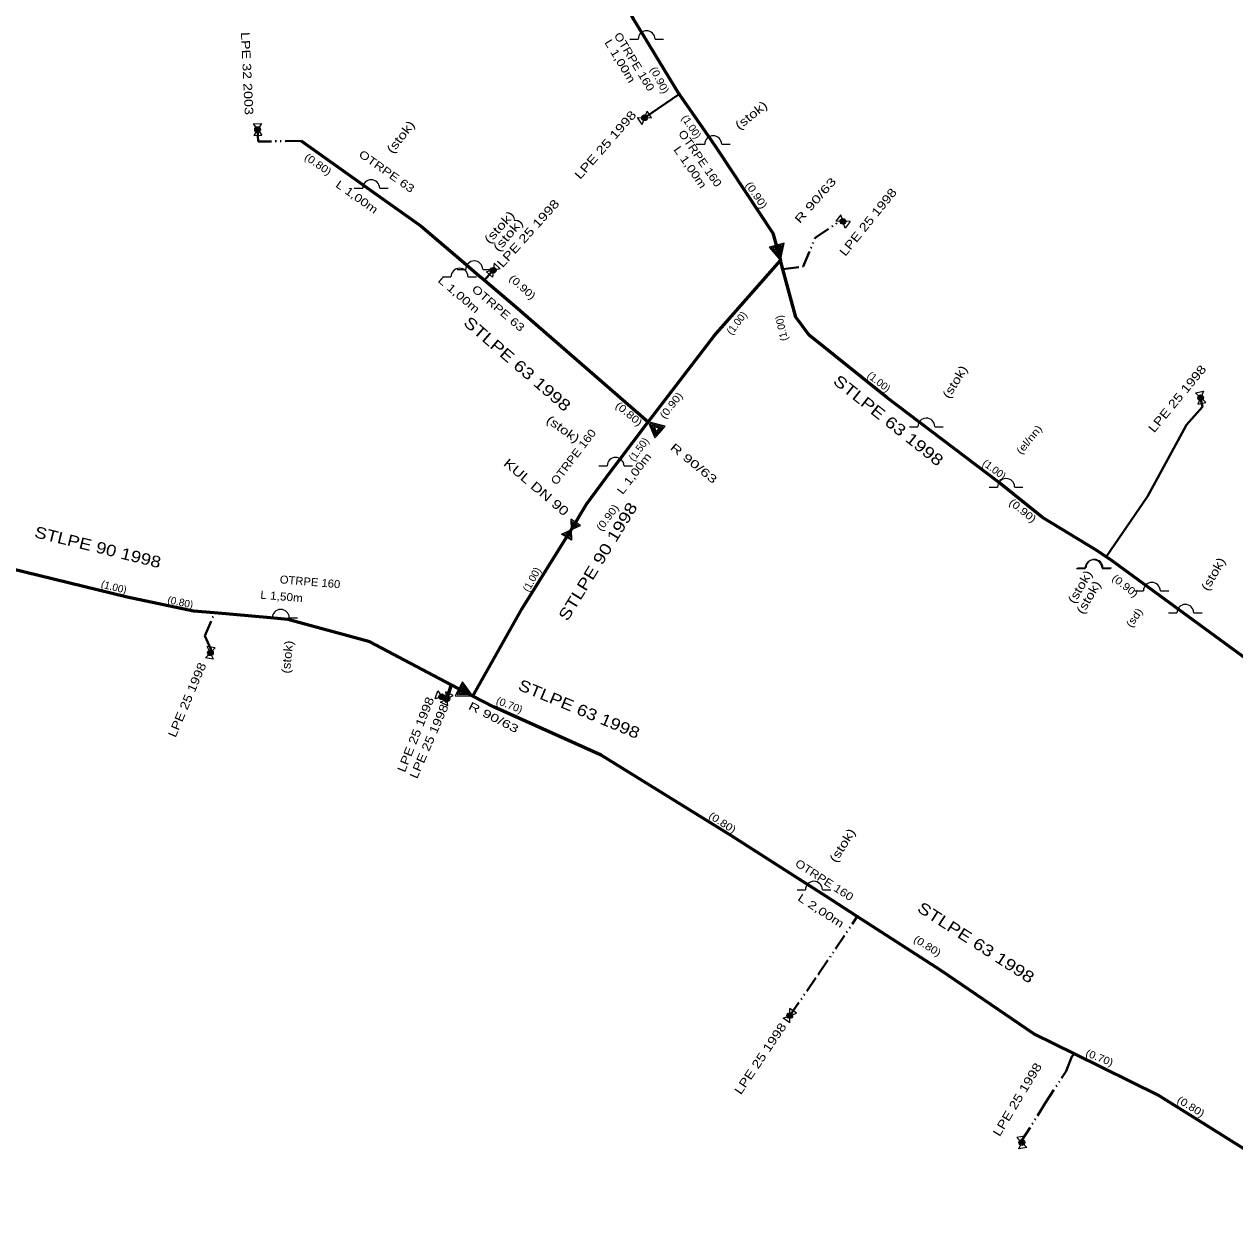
# Model space of a CAD drawing. Extents: x -648036 to -642998, y -1161549 to -1158141.
# Drawn here: x -646444.5 to -646338.6, y -1161075.7 to -1160970.1 of the extents above; entities that cross this region are included whole.
import ezdxf
from ezdxf.enums import TextEntityAlignment as Align

# ---------------------------------------------------------------- set-up
doc = ezdxf.new("R2010")
doc.units = 0
doc.header["$LTSCALE"] = 0.28
doc.linetypes.add('DASH_DOUBLE_DOT', pattern=[9.2, 5, -1.2, 0.3, -1.2, 0.3, -1.2])
for name, color, linetype, lineweight in [('12', 7, 'DASH_DOUBLE_DOT', 40), ('14', 7, 'Continuous', 13), ('15', 7, 'Continuous', 13), ('19', 7, 'Continuous', 13), ('8', 7, 'Continuous', 53)]:
    doc.layers.add(name, color=color, linetype=linetype, lineweight=lineweight)
for name, color, linetype in [('20', 7, 'Continuous'), ('22', 7, 'Continuous'), ('24', 7, 'Continuous'), ('25', 7, 'Continuous'), ('27', 7, 'Continuous'), ('28', 7, 'Continuous'), ('35', 7, 'Continuous')]:
    doc.layers.add(name, color=color, linetype=linetype)

msp = doc.modelspace()

# ---------------------------------------------------------------- linework, layer by layer
at = {"layer": '12', "linetype": 'Continuous'}
msp.add_line((-646390.24, -1160978.3), (-646387.22, -1160976.24), dxfattribs=at)
at = {"layer": '12'}
for p, q in [((-646403.47, -1160991.64), (-646404.24, -1160992.5)), ((-646407.52, -1161029.09), (-646407.97, -1161028.93)), ((-646407.52, -1161029.09), (-646407.53, -1161029.11))]:
    msp.add_line(p, q, dxfattribs=at)
for points in [[(-646420.27, -1160980.33), (-646424.03, -1160980.38), (-646424.08, -1160979.33)], [(-646378.14, -1160991.54), (-646376.36, -1160991.3), (-646375.31, -1160988.79), (-646373.04, -1160987.25), (-646372.89, -1160987.36)], [(-646428.21, -1161025.08), (-646428.16, -1161024.77), (-646428.69, -1161023.6), (-646427.84, -1161021.6)], [(-646377.54, -1161056.82), (-646374.99, -1161053.14), (-646371.64, -1161048.15)], [(-646357.25, -1161067.91), (-646357.27, -1161067.78), (-646355.2, -1161064.47), (-646353.37, -1161061.66), (-646352.87, -1161060.4), (-646352.64, -1161060.17)]]:
    msp.add_lwpolyline(points, dxfattribs=at)
at = {"layer": '12', "linetype": 'Continuous'}
msp.add_lwpolyline([(-646349.88, -1161016.69), (-646346.27, -1161011.41), (-646343.78, -1161006.86), (-646342.86, -1161005.15), (-646341.45, -1161003.58), (-646341.61, -1161002.78)], dxfattribs=at)
at = {"layer": '14'}
for p, q in [((-646389.87, -1160971.88), (-646390.39, -1160971.02)), ((-646383.91, -1160981), (-646384.48, -1160980.18)), ((-646413.88, -1160984.86), (-646414.69, -1160984.28)), ((-646406.04, -1160990.96), (-646404.9, -1160991.94)), ((-646393.19, -1161009.21), (-646392.53, -1161008.33)), ((-646422.94, -1161022.04), (-646421.44, -1161022.17)), ((-646374.39, -1161046.37), (-646376.07, -1161045.29))]:
    msp.add_line(p, q, dxfattribs=at)
at = {"layer": '15'}
for p, q in [((-646391.535, -1160971.435), (-646390.8, -1160971.434)), ((-646389.314, -1160971.434), (-646388.58, -1160971.435)), ((-646390.857, -1160978.29), (-646389.624, -1160978.311)), ((-646390.456, -1160978.878), (-646390.857, -1160978.29)), ((-646390.456, -1160978.878), (-646390.024, -1160977.722)), ((-646389.624, -1160978.311), (-646390.024, -1160977.722)), ((-646424.46, -1160978.844), (-646423.748, -1160978.81)), ((-646424.46, -1160978.844), (-646423.7, -1160979.816)), ((-646423.748, -1160978.81), (-646424.412, -1160979.849)), ((-646424.412, -1160979.849), (-646423.7, -1160979.816)), ((-646385.715, -1160980.615), (-646384.98, -1160980.614)), ((-646383.494, -1160980.614), (-646382.76, -1160980.615)), ((-646415.625, -1160984.465), (-646414.89, -1160984.464)), ((-646413.404, -1160984.464), (-646412.67, -1160984.465)), ((-646373.085, -1160986.775), (-646373.507, -1160987.349)), ((-646372.694, -1160987.945), (-646373.085, -1160986.775)), ((-646372.273, -1160987.371), (-646373.507, -1160987.349)), ((-646372.273, -1160987.371), (-646372.694, -1160987.945)), ((-646403.399, -1160991.027), (-646403.541, -1160992.253)), ((-646403.399, -1160991.027), (-646402.869, -1160991.502)), ((-646406.615, -1160991.565), (-646405.88, -1160991.564)), ((-646404.394, -1160991.564), (-646403.66, -1160991.565)), ((-646402.869, -1160991.502), (-646404.071, -1160991.777)), ((-646404.071, -1160991.777), (-646403.541, -1160992.253)), ((-646407.905, -1160992.205), (-646407.17, -1160992.204)), ((-646405.684, -1160992.204), (-646404.95, -1160992.205)), ((-646342.058, -1161002.356), (-646341.36, -1161002.216)), ((-646342.058, -1161002.356), (-646341.162, -1161003.204)), ((-646341.36, -1161002.216), (-646341.86, -1161003.343)), ((-646341.86, -1161003.343), (-646341.162, -1161003.204)), ((-646367.075, -1161005.315), (-646366.34, -1161005.314)), ((-646364.854, -1161005.314), (-646364.12, -1161005.315)), ((-646394.245, -1161008.745), (-646393.51, -1161008.744)), ((-646392.024, -1161008.744), (-646391.29, -1161008.745)), ((-646360.105, -1161010.595), (-646359.37, -1161010.594)), ((-646357.884, -1161010.594), (-646357.15, -1161010.595)), ((-646396.695, -1161013.539), (-646395.951, -1161014.003)), ((-646396.69, -1161013.698), (-646396.094, -1161014.069)), ((-646396.686, -1161013.846), (-646396.23, -1161014.13)), ((-646396.681, -1161014.01), (-646396.379, -1161014.197)), ((-646396.675, -1161014.174), (-646396.528, -1161014.265)), ((-646397.357, -1161014.642), (-646396.646, -1161015.085)), ((-646397.206, -1161014.573), (-646396.651, -1161014.918)), ((-646397.078, -1161014.514), (-646396.656, -1161014.777)), ((-646396.967, -1161014.464), (-646396.66, -1161014.654)), ((-646396.822, -1161014.398), (-646396.665, -1161014.497)), ((-646352.455, -1161017.705), (-646351.72, -1161017.704)), ((-646352.375, -1161017.665), (-646351.64, -1161017.664)), ((-646350.234, -1161017.704), (-646349.5, -1161017.705)), ((-646350.154, -1161017.664), (-646349.42, -1161017.665)), ((-646347.355, -1161019.675), (-646346.62, -1161019.674)), ((-646345.134, -1161019.674), (-646344.4, -1161019.675)), ((-646344.425, -1161021.605), (-646343.69, -1161021.604)), ((-646342.204, -1161021.604), (-646341.47, -1161021.605)), ((-646423.535, -1161022.035), (-646422.8, -1161022.034)), ((-646421.314, -1161022.034), (-646420.58, -1161022.035)), ((-646428.642, -1161025.521), (-646427.778, -1161024.64)), ((-646427.778, -1161024.64), (-646428.481, -1161024.526)), ((-646427.939, -1161025.634), (-646428.481, -1161024.526)), ((-646427.939, -1161025.634), (-646428.642, -1161025.521)), ((-646408.564, -1161029.097), (-646408.326, -1161028.426)), ((-646408.564, -1161029.097), (-646407.376, -1161028.763)), ((-646408.326, -1161028.426), (-646407.615, -1161029.434)), ((-646408.074, -1161029.402), (-646406.987, -1161028.819)), ((-646406.987, -1161028.819), (-646407.623, -1161028.5)), ((-646407.437, -1161029.72), (-646407.623, -1161028.5)), ((-646407.615, -1161029.434), (-646407.376, -1161028.763)), ((-646407.437, -1161029.72), (-646408.074, -1161029.402)), ((-646376.905, -1161045.815), (-646376.17, -1161045.814)), ((-646374.684, -1161045.814), (-646373.95, -1161045.815)), ((-646378.12, -1161057.032), (-646376.961, -1161056.609)), ((-646376.961, -1161056.609), (-646377.546, -1161056.203)), ((-646377.534, -1161057.437), (-646377.546, -1161056.203)), ((-646377.534, -1161057.437), (-646378.12, -1161057.032)), ((-646356.975, -1161067.359), (-646357.678, -1161067.466)), ((-646356.822, -1161068.354), (-646357.678, -1161067.466)), ((-646357.525, -1161068.462), (-646356.975, -1161067.359)), ((-646356.822, -1161068.354), (-646357.525, -1161068.462))]:
    msp.add_line(p, q, dxfattribs=at)
for points in [[(-646379.351, -1160989.607), (-646378.34, -1160990.77), (-646378.022, -1160989.262), (-646378.687, -1160989.434)], [(-646379.17, -1160989.663), (-646378.397, -1160990.552), (-646378.154, -1160989.399)], [(-646378.987, -1160989.719), (-646378.452, -1160990.335), (-646378.284, -1160989.536)], [(-646378.806, -1160989.775), (-646378.508, -1160990.117), (-646378.416, -1160989.674)], [(-646388.428, -1161005.266), (-646389.92, -1161004.88), (-646389.328, -1161006.303), (-646388.878, -1161005.784)], [(-646388.609, -1161005.322), (-646389.75, -1161005.027), (-646389.297, -1161006.115)], [(-646388.791, -1161005.38), (-646389.581, -1161005.175), (-646389.267, -1161005.928)], [(-646388.972, -1161005.436), (-646389.411, -1161005.322), (-646389.236, -1161005.74)], [(-646396.67, -1161014.33), (-646396.641, -1161015.249), (-646397.507, -1161014.709), (-646395.833, -1161013.95), (-646396.699, -1161013.411)], [(-646406.801, -1161028.839), (-646405.26, -1161028.87), (-646406.165, -1161027.622), (-646406.483, -1161028.231)], [(-646406.638, -1161028.743), (-646405.459, -1161028.766), (-646406.152, -1161027.812)], [(-646406.474, -1161028.645), (-646405.658, -1161028.661), (-646406.137, -1161028.001)], [(-646406.31, -1161028.548), (-646405.857, -1161028.557), (-646406.124, -1161028.191)]]:
    msp.add_lwpolyline(points, close=True, dxfattribs=at)
for centre in [(-646390.0574, -1160971.4346), (-646384.2374, -1160980.6146), (-646414.1474, -1160984.4646), (-646405.1374, -1160991.5646), (-646406.4274, -1160992.2046), (-646365.5974, -1161005.3146), (-646392.7674, -1161008.7446), (-646358.6274, -1161010.5946), (-646350.9774, -1161017.7046), (-646350.8974, -1161017.6646), (-646345.8774, -1161019.6746), (-646422.0574, -1161022.0346), (-646342.9474, -1161021.6046), (-646375.4274, -1161045.8146)]:
    msp.add_arc(centre, 0.7431, 1.2748, 179.83951, dxfattribs=at)
at = {"layer": '19'}
for centre, radius in [((-646390.24, -1160978.3), 0.25), ((-646390.24, -1160978.3), 0.17), ((-646390.24, -1160978.3), 0.09), ((-646424.08, -1160979.33), 0.25), ((-646424.08, -1160979.33), 0.17), ((-646424.08, -1160979.33), 0.09), ((-646372.89, -1160987.36), 0.25), ((-646372.89, -1160987.36), 0.17), ((-646372.89, -1160987.36), 0.09), ((-646403.47, -1160991.64), 0.25), ((-646403.47, -1160991.64), 0.17), ((-646403.47, -1160991.64), 0.09), ((-646341.61, -1161002.78), 0.25), ((-646341.61, -1161002.78), 0.17), ((-646341.61, -1161002.78), 0.09), ((-646428.21, -1161025.08), 0.25), ((-646428.21, -1161025.08), 0.17), ((-646428.21, -1161025.08), 0.09), ((-646407.97, -1161028.93), 0.25), ((-646407.97, -1161028.93), 0.17), ((-646407.97, -1161028.93), 0.09), ((-646407.53, -1161029.11), 0.25), ((-646407.53, -1161029.11), 0.17), ((-646407.53, -1161029.11), 0.09), ((-646377.54, -1161056.82), 0.25), ((-646377.54, -1161056.82), 0.17), ((-646377.54, -1161056.82), 0.09), ((-646357.25, -1161067.91), 0.25), ((-646357.25, -1161067.91), 0.17), ((-646357.25, -1161067.91), 0.09)]:
    msp.add_circle(centre, radius, dxfattribs=at)
at = {"layer": '8', "linetype": 'DASH_DOUBLE_DOT'}
msp.add_line((-646407.14, -1161027.88), (-646407.52, -1161029.09), dxfattribs=at)
at = {"layer": '8'}
msp.add_line((-646405.26, -1161028.87), (-646407.14, -1161027.88), dxfattribs=at)
for points in [[(-646392.83, -1160966.59), (-646391.17, -1160969.75), (-646390.39, -1160971.02), (-646389.87, -1160971.88), (-646387.23, -1160976.21), (-646387.22, -1160976.24)], [(-646387.22, -1160976.24), (-646384.48, -1160980.18), (-646383.91, -1160981), (-646379.03, -1160988.38), (-646378.34, -1160990.77)], [(-646420.27, -1160980.33), (-646414.69, -1160984.28), (-646413.88, -1160984.86), (-646409.77, -1160987.77), (-646406.04, -1160990.96), (-646404.9, -1160991.94), (-646404.24, -1160992.5)], [(-646389.92, -1161004.88), (-646389.82, -1161004.74), (-646384.16, -1160997.36), (-646378.34, -1160990.77)], [(-646349.88, -1161016.69), (-646350.68, -1161016.13), (-646355.44, -1161013.25), (-646359.33, -1161010.13), (-646369.06, -1161002.76), (-646375.84, -1160997.32), (-646377.01, -1160995.74), (-646378.14, -1160991.54), (-646378.34, -1160990.77)], [(-646404.24, -1160992.5), (-646401.53, -1160994.81), (-646389.92, -1161004.88)], [(-646396.67, -1161014.33), (-646395.31, -1161012.09), (-646393.19, -1161009.21), (-646392.53, -1161008.33), (-646389.92, -1161004.88)], [(-646427.84, -1161021.6), (-646429.68, -1161021.44), (-646435.5, -1161020.22), (-646445.76, -1161017.71), (-646448.11, -1161014.72), (-646465.36, -1161010.93)], [(-646405.26, -1161028.87), (-646400.95, -1161021.21), (-646396.67, -1161014.33)], [(-646325.14, -1161034.26), (-646329.72, -1161031.16), (-646335.55, -1161027.12), (-646345.12, -1161020.14), (-646349.47, -1161016.97), (-646349.88, -1161016.69)], [(-646407.14, -1161027.88), (-646414.27, -1161024.13), (-646421.44, -1161022.17), (-646422.94, -1161022.04), (-646427.84, -1161021.6)], [(-646371.64, -1161048.15), (-646374.39, -1161046.37), (-646376.07, -1161045.29), (-646382.63, -1161041.09), (-646394.05, -1161034.03), (-646403.46, -1161029.81), (-646405.26, -1161028.87)], [(-646352.64, -1161060.17), (-646356.21, -1161058.41), (-646364.37, -1161052.85), (-646371.64, -1161048.15)], [(-646327.39, -1161075.72), (-646334.04, -1161070.83), (-646345.33, -1161063.76), (-646352.64, -1161060.17)]]:
    msp.add_lwpolyline(points, dxfattribs=at)

# ---------------------------------------------------------------- texts
at = {"layer": '20'}
for s, rotation, width, p in [('STLPE 63 1998', 319.138, 1.25, (-646401.6966, -1161000.2027)), ('STLPE 63 1998', 321.429, 1.25, (-646369.2242, -1161005.161)), ('STLPE 90 1998', 58.442, 1.25, (-646393.8969, -1161017.3637)), ('STLPE 90 1998', 346.067, 1.2, (-646438.1669, -1161016.334)), ('STLPE 63 1998', 337.472, 1.2, (-646396.1551, -1161030.4654)), ('STLPE 63 1998', 327.159, 1.25, (-646361.5292, -1161050.8425))]:
    msp.add_text(s, height=1, rotation=rotation, dxfattribs=dict(at, width=width)).set_placement(p, align=Align.CENTER)
at = {"layer": '22'}
for s, rotation, width, p in [('LPE 32 2003', 272.728, 1.25, (-646425.3655, -1160974.4482)), ('LPE 25 1998', 48.701, 1.3, (-646393.3878, -1160980.9165)), ('LPE 25 1998', 50.993, 1.25, (-646370.4041, -1160987.6565)), ('LPE 25 1998', 48.128, 1.3, (-646400.1435, -1160988.6613)), ('LPE 25 1998', 50.42, 1.25, (-646343.3703, -1161003.1099)), ('LPE 25 1998', 67.036, 1.2, (-646429.8992, -1161029.3498)), ('LPE 25 1998', 68.182, 1.2, (-646409.9092, -1161032.3699)), ('LPE 25 1998', 66.463, 1.2, (-646408.7489, -1161032.9753)), ('LPE 25 1998', 56.15, 1.25, (-646379.803, -1161060.7799)), ('LPE 25 1998', 59.015, 1.25, (-646357.3238, -1161064.3441))]:
    msp.add_text(s, height=0.75, rotation=rotation, dxfattribs=dict(at, width=width)).set_placement(p, align=Align.CENTER)
at = {"layer": '24'}
for s, rotation, width, p in [('OTRPE 160', 301.376, 1.15, (-646391.4333, -1160973.5783)), ('L 1,00m', 301.376, 1.25, (-646392.6816, -1160973.5183)), ('OTRPE 160', 304.814, 1.15, (-646385.6733, -1160982.0517)), ('OTRPE 63', 324.867, 1.25, (-646412.9899, -1160983.2735)), ('L 1,00m', 304.814, 1.25, (-646386.5319, -1160982.8207)), ('L 1,00m', 324.867, 1.25, (-646415.5974, -1160985.5117)), ('L 1,00m', 319.71, 1.3, (-646406.7038, -1160994.0292)), ('OTRPE 63', 319.71, 1.25, (-646403.2568, -1160995.224)), ('OTRPE 160', 52.712, 1.15, (-646396.1878, -1161008.172)), ('L 1,00m', 52.712, 1.25, (-646390.8747, -1161009.6245)), ('OTRPE 160', 355.234, 1.05, (-646419.5211, -1161019.227)), ('L 1,50m', 355.234, 1.1, (-646422.0096, -1161020.507)), ('OTRPE 160', 327.159, 1.15, (-646374.7023, -1161045.2549)), ('L 2,00m', 327.159, 1.35, (-646375.0053, -1161047.9312))]:
    msp.add_text(s, height=0.7, rotation=rotation, dxfattribs=dict(at, width=width)).set_placement(p, align=Align.CENTER)
at = {"layer": '25'}
for rotation, width, p in [(48.701, 1.5, (-646375.0427, -1160985.7515)), (320.856, 1.5, (-646386.1564, -1161008.7914)), (332.888, 1.45, (-646403.598, -1161031.0479))]:
    msp.add_text('R 90/63', height=0.7, rotation=rotation, dxfattribs=dict(at, width=width)).set_placement(p, align=Align.CENTER)
at = {"layer": '27'}
for s, rotation, width, p in [('(0.90)', 297.365, 1.1, (-646389.211, -1160975.1561)), ('(0.80)', 325.44, 1.15, (-646418.9759, -1160982.6276)), ('(0.90)', 304.241, 1.15, (-646380.7246, -1160985.2466)), ('(0.90)', 317.992, 1.2, (-646401.1395, -1160993.3457)), ('(0.90)', 52.139, 1.15, (-646387.6593, -1161003.653)), ('(0.80)', 319.71, 1.2, (-646391.8132, -1161004.4389)), ('(el/nn)', 50.993, 1.2, (-646356.3559, -1161006.6556)), ('(0.90)', 53.285, 1.15, (-646393.2272, -1161013.4593)), ('(0.90)', 320.856, 1.2, (-646357.3757, -1161012.9012)), ('(0.90)', 322.002, 1.15, (-646348.4121, -1161019.4825)), ('(sd)', 55.004, 1.2, (-646347.1486, -1161022.2079)), ('(0.70)', 338.618, 1.05, (-646402.178, -1161029.9504)), ('(0.80)', 327.159, 1.15, (-646383.6063, -1161040.2079)), ('(0.80)', 328.305, 1.15, (-646365.6733, -1161050.9914)), ('(0.70)', 338.045, 1.1, (-646350.575, -1161060.7919)), ('(0.80)', 328.305, 1.15, (-646342.6333, -1161065.0414))]:
    msp.add_text(s, height=0.65, rotation=rotation, dxfattribs=dict(at, width=width)).set_placement(p, align=Align.CENTER)
for s, rotation, p in [('(1.00)', 304.241, (-646386.4088, -1160979.2651)), ('(1.00)', 52.712, (-646381.9215, -1160996.4459)), ('(1.00)', 102.559, (-646377.9494, -1160996.6312)), ('(1.00)', 322.002, (-646369.9506, -1161001.6443)), ('(1.50)', 53.858, (-646390.4857, -1161007.4872)), ('(1.00)', 323.148, (-646359.8489, -1161009.3058)), ('(1.00)', 61.306, (-646399.8148, -1161018.83)), ('(1.00)', 346.067, (-646436.7228, -1161019.6491)), ('(0.80)', 347.785, (-646430.9008, -1161020.9789))]:
    msp.add_text(s, height=0.65, rotation=rotation, dxfattribs=at).set_placement(p, align=Align.CENTER)
at = {"layer": '28'}
for rotation, width, p in [(38.961, 1.3, (-646380.6843, -1160978.371)), (52.139, 1.3, (-646411.2739, -1160980.2087)), (48.128, 1.35, (-646402.6618, -1160988.1238)), (49.847, 1.35, (-646401.8952, -1160988.7903)), (58.442, 1.25, (-646362.7752, -1161001.5938)), (324.294, 1.3, (-646397.5874, -1161005.8294)), (60.161, 1.25, (-646340.1819, -1161018.3906)), (59.588, 1.25, (-646351.8368, -1161019.5083)), (59.588, 1.25, (-646351.0868, -1161020.4283)), (84.225, 1.15, (-646421.1117, -1161025.4932)), (57.869, 1.3, (-646372.6197, -1161042.1314))]:
    msp.add_text('(stok)', height=0.75, rotation=rotation, dxfattribs=dict(at, width=width)).set_placement(p, align=Align.CENTER)
at = {"layer": '35', "width": 1.3}
msp.add_text('KUL DN 90', height=0.8, rotation=319.71, dxfattribs=at).set_placement((-646399.9662, -1161010.9096), align=Align.CENTER)

doc.saveas('drawing.dxf')
